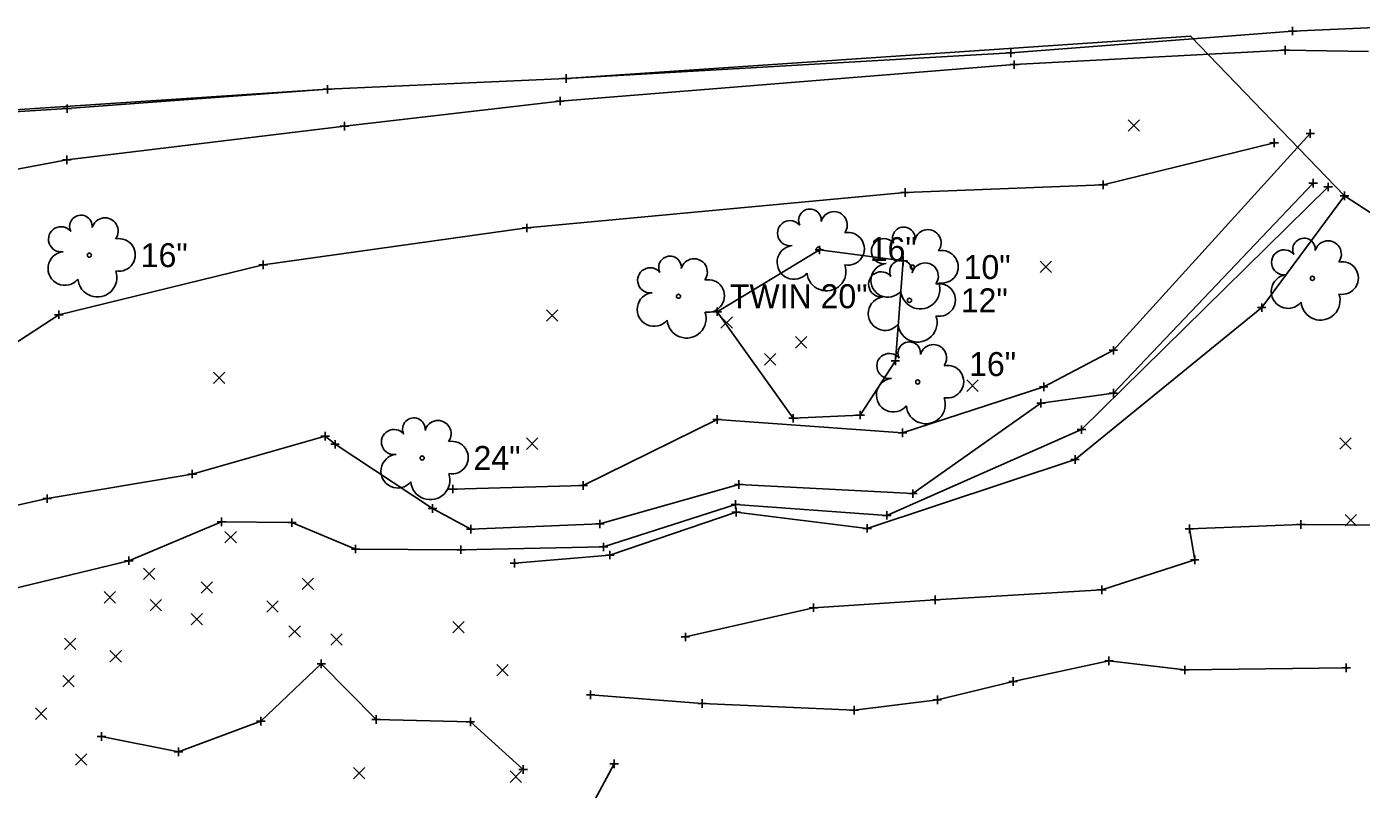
# Model space of a CAD drawing. Extents: x 203564 to 204038, y 344976 to 345157.
# Drawn here: x 203796.6 to 203952.6, y 345067.2 to 345156.4 of the extents above; entities that cross this region are included whole.
import ezdxf

# ---------------------------------------------------------------- set-up
doc = ezdxf.new("R2010")
doc.units = 0
for name, color, linetype in [('_CIVIL_CONSTRUCTION', 7, 'Continuous'), ('DR_X_Ditch', 7, 'Continuous'), ('RD_X_Fence', 7, 'Continuous'), ('RW_X_CL_100_Bearings', 7, 'Continuous'), ('RW_X_CL_100_Cardinal_Points', 7, 'Continuous'), ('SV_X_Break_Lines', 7, 'Continuous'), ('SV_X_Edge_of_Slip', 7, 'Continuous'), ('SV_X_Terrain_Boundary', 7, 'Continuous'), ('SV_X_Top_of_Bank', 7, 'Continuous'), ('VG_X_Text', 7, 'Continuous')]:
    doc.layers.add(name, color=color, linetype=linetype)

msp = doc.modelspace()

# ---------------------------------------------------------------- linework, layer by layer
at = {"layer": '_CIVIL_CONSTRUCTION'}
for p, q in [((203944.06, 345155.88), (203945.06, 345155.88)), ((203944.56, 345156.38), (203944.56, 345155.38)), ((203944.56, 345155.88), (203944.56, 345155.88)), ((203911.63, 345153.84), (203911.63, 345152.84)), ((203943.72, 345154.14), (203943.72, 345153.14)), ((203911.13, 345153.34), (203912.13, 345153.34)), ((203911.63, 345153.34), (203911.63, 345153.34)), ((203912.05, 345152.45), (203912.05, 345151.45)), ((203943.22, 345153.64), (203944.22, 345153.64)), ((203943.72, 345153.64), (203943.72, 345153.64)), ((203859.66, 345150.84), (203859.66, 345149.84)), ((203911.55, 345151.95), (203912.55, 345151.95)), ((203912.05, 345151.95), (203912.05, 345151.95)), ((203831.78, 345149.57), (203831.78, 345148.57)), ((203859.16, 345150.34), (203860.16, 345150.34)), ((203859.66, 345150.34), (203859.66, 345150.34)), ((203831.28, 345149.07), (203832.28, 345149.07)), ((203831.78, 345149.07), (203831.78, 345149.07)), ((203858.46, 345147.7), (203859.46, 345147.7)), ((203858.96, 345148.2), (203858.96, 345147.2)), ((203858.96, 345147.7), (203858.96, 345147.7)), ((203800.86, 345146.81), (203801.86, 345146.81)), ((203801.36, 345147.31), (203801.36, 345146.31)), ((203801.36, 345146.81), (203801.36, 345146.81)), ((203833.26, 345144.76), (203834.26, 345144.76)), ((203833.76, 345145.26), (203833.76, 345144.26)), ((203833.76, 345144.76), (203833.76, 345144.76)), ((203942.42, 345143.3), (203942.42, 345142.3)), ((203946.15, 345143.9), (203947.15, 345143.9)), ((203946.65, 345144.4), (203946.65, 345143.4)), ((203946.65, 345143.9), (203946.65, 345143.9)), ((203801.31, 345141.31), (203801.31, 345140.31)), ((203941.92, 345142.8), (203942.92, 345142.8)), ((203942.42, 345142.8), (203942.42, 345142.8)), ((203800.81, 345140.81), (203801.81, 345140.81)), ((203801.31, 345140.81), (203801.31, 345140.81)), ((203922.44, 345138.4), (203922.44, 345137.4)), ((203946.98, 345138.58), (203946.98, 345137.58)), ((203898.78, 345137.01), (203899.78, 345137.01)), ((203899.28, 345137.51), (203899.28, 345136.51)), ((203899.28, 345137.01), (203899.28, 345137.01)), ((203921.94, 345137.9), (203922.94, 345137.9)), ((203922.44, 345137.9), (203922.44, 345137.9)), ((203946.48, 345138.08), (203947.48, 345138.08)), ((203946.98, 345138.08), (203946.98, 345138.08)), ((203948.24, 345137.65), (203949.24, 345137.65)), ((203948.74, 345138.15), (203948.74, 345137.15)), ((203948.74, 345137.65), (203948.74, 345137.65)), ((203950.66, 345137.11), (203950.66, 345136.11)), ((203950.16, 345136.61), (203951.16, 345136.61)), ((203950.66, 345136.61), (203950.66, 345136.61)), ((203854.57, 345132.85), (203855.57, 345132.85)), ((203855.07, 345133.35), (203855.07, 345132.35)), ((203855.07, 345132.85), (203855.07, 345132.85)), ((203889.27, 345130.78), (203889.27, 345129.78)), ((203824.26, 345129.04), (203824.26, 345128.04)), ((203888.77, 345130.28), (203889.77, 345130.28)), ((203889.27, 345130.28), (203889.27, 345130.28)), ((203898.57, 345129.02), (203899.57, 345129.02)), ((203899.07, 345129.52), (203899.07, 345128.52)), ((203899.07, 345129.02), (203899.07, 345129.02)), ((203823.76, 345128.54), (203824.76, 345128.54)), ((203824.26, 345128.54), (203824.26, 345128.54)), ((203799.89, 345122.71), (203800.89, 345122.71)), ((203800.39, 345123.21), (203800.39, 345122.21)), ((203800.39, 345122.71), (203800.39, 345122.71)), ((203876.84, 345123.06), (203877.84, 345123.06)), ((203877.34, 345123.56), (203877.34, 345122.56)), ((203877.34, 345123.06), (203877.34, 345123.06)), ((203940.47, 345123.54), (203941.47, 345123.54)), ((203940.97, 345124.04), (203940.97, 345123.04)), ((203940.97, 345123.54), (203940.97, 345123.54)), ((203923.13, 345118.55), (203924.13, 345118.55)), ((203923.63, 345119.05), (203923.63, 345118.05)), ((203923.63, 345118.55), (203923.63, 345118.55)), ((203897.65, 345117.32), (203898.65, 345117.32)), ((203898.15, 345117.82), (203898.15, 345116.82)), ((203898.15, 345117.32), (203898.15, 345117.32)), ((203915.49, 345114.78), (203915.49, 345113.78)), ((203914.99, 345114.28), (203915.99, 345114.28)), ((203915.49, 345114.28), (203915.49, 345114.28)), ((203923.13, 345113.53), (203924.13, 345113.53)), ((203923.63, 345114.03), (203923.63, 345113.03)), ((203923.63, 345113.53), (203923.63, 345113.53)), ((203914.67, 345112.36), (203915.67, 345112.36)), ((203915.17, 345112.86), (203915.17, 345111.86)), ((203915.17, 345112.36), (203915.17, 345112.36)), ((203876.83, 345110.45), (203877.83, 345110.45)), ((203877.33, 345110.95), (203877.33, 345109.95)), ((203877.33, 345110.45), (203877.33, 345110.45)), ((203885.7, 345110.6), (203886.7, 345110.6)), ((203886.2, 345111.1), (203886.2, 345110.1)), ((203886.2, 345110.6), (203886.2, 345110.6)), ((203893.54, 345110.98), (203894.54, 345110.98)), ((203894.04, 345111.48), (203894.04, 345110.48)), ((203894.04, 345110.98), (203894.04, 345110.98)), ((203831.51, 345109.02), (203831.51, 345108.02)), ((203898.5, 345108.9), (203899.5, 345108.9)), ((203899, 345109.4), (203899, 345108.4)), ((203899, 345108.9), (203899, 345108.9)), ((203919.42, 345109.27), (203920.42, 345109.27)), ((203919.92, 345109.77), (203919.92, 345108.77)), ((203919.92, 345109.27), (203919.92, 345109.27)), ((203831.01, 345108.52), (203832.01, 345108.52)), ((203831.51, 345108.52), (203831.51, 345108.52)), ((203832.16, 345107.56), (203833.16, 345107.56)), ((203832.66, 345108.06), (203832.66, 345107.06)), ((203832.66, 345107.56), (203832.66, 345107.56)), ((203918.65, 345105.79), (203919.65, 345105.79)), ((203919.15, 345106.29), (203919.15, 345105.29)), ((203919.15, 345105.79), (203919.15, 345105.79)), ((203815.46, 345104.08), (203816.46, 345104.08)), ((203815.96, 345104.58), (203815.96, 345103.58)), ((203815.96, 345104.08), (203815.96, 345104.08)), ((203845.92, 345102.33), (203846.92, 345102.33)), ((203846.42, 345102.83), (203846.42, 345101.83)), ((203846.42, 345102.33), (203846.42, 345102.33)), ((203861.16, 345102.75), (203862.16, 345102.75)), ((203861.66, 345103.25), (203861.66, 345102.25)), ((203861.66, 345102.75), (203861.66, 345102.75)), ((203879.35, 345102.86), (203880.35, 345102.86)), ((203879.85, 345103.36), (203879.85, 345102.36)), ((203879.85, 345102.86), (203879.85, 345102.86)), ((203798.52, 345101.2), (203799.52, 345101.2)), ((203799.02, 345101.7), (203799.02, 345100.7)), ((203799.02, 345101.2), (203799.02, 345101.2)), ((203879.46, 345101.01), (203879.46, 345100.01)), ((203899.71, 345101.79), (203900.71, 345101.79)), ((203900.21, 345102.29), (203900.21, 345101.29)), ((203900.21, 345101.79), (203900.21, 345101.79)), ((203843.56, 345100.06), (203844.56, 345100.06)), ((203844.06, 345100.56), (203844.06, 345099.56)), ((203844.06, 345100.06), (203844.06, 345100.06)), ((203878.96, 345100.51), (203879.96, 345100.51)), ((203879.04, 345099.63), (203880.04, 345099.63)), ((203879.46, 345100.51), (203879.46, 345100.51)), ((203879.54, 345100.13), (203879.54, 345099.13)), ((203879.54, 345099.63), (203879.54, 345099.63)), ((203896.66, 345099.25), (203897.66, 345099.25)), ((203897.16, 345099.75), (203897.16, 345098.75)), ((203897.16, 345099.25), (203897.16, 345099.25)), ((203818.9, 345098.49), (203819.9, 345098.49)), ((203819.4, 345098.99), (203819.4, 345097.99)), ((203819.4, 345098.49), (203819.4, 345098.49)), ((203827.13, 345098.4), (203828.13, 345098.4)), ((203827.63, 345098.9), (203827.63, 345097.9)), ((203827.63, 345098.4), (203827.63, 345098.4)), ((203848.02, 345097.64), (203849.02, 345097.64)), ((203848.52, 345098.14), (203848.52, 345097.14)), ((203848.52, 345097.64), (203848.52, 345097.64)), ((203863.13, 345098.24), (203864.13, 345098.24)), ((203863.63, 345098.74), (203863.63, 345097.74)), ((203863.63, 345098.24), (203863.63, 345098.24)), ((203894.37, 345097.73), (203895.37, 345097.73)), ((203894.87, 345098.23), (203894.87, 345097.23)), ((203894.87, 345097.73), (203894.87, 345097.73)), ((203932.02, 345097.67), (203933.02, 345097.67)), ((203932.52, 345098.17), (203932.52, 345097.17)), ((203932.52, 345097.67), (203932.52, 345097.67)), ((203945.04, 345098.18), (203946.04, 345098.18)), ((203945.54, 345098.68), (203945.54, 345097.68)), ((203945.54, 345098.18), (203945.54, 345098.18)), ((203834.57, 345095.31), (203835.57, 345095.31)), ((203835.07, 345095.81), (203835.07, 345094.81)), ((203835.07, 345095.31), (203835.07, 345095.31)), ((203846.88, 345095.23), (203847.88, 345095.23)), ((203847.38, 345095.73), (203847.38, 345094.73)), ((203847.38, 345095.23), (203847.38, 345095.23)), ((203863.54, 345095.55), (203864.54, 345095.55)), ((203864.04, 345096.05), (203864.04, 345095.05)), ((203864.04, 345095.55), (203864.04, 345095.55)), ((203864.28, 345094.61), (203865.28, 345094.61)), ((203864.78, 345095.11), (203864.78, 345094.11)), ((203864.78, 345094.61), (203864.78, 345094.61)), ((203933.14, 345094.54), (203933.14, 345093.54)), ((203808.07, 345093.95), (203809.07, 345093.95)), ((203808.57, 345094.45), (203808.57, 345093.45)), ((203808.57, 345093.95), (203808.57, 345093.95)), ((203853.12, 345093.67), (203854.12, 345093.67)), ((203853.62, 345094.17), (203853.62, 345093.17)), ((203853.62, 345093.67), (203853.62, 345093.67)), ((203932.64, 345094.04), (203933.64, 345094.04)), ((203933.14, 345094.04), (203933.14, 345094.04)), ((203902.81, 345089.86), (203902.81, 345088.86)), ((203921.79, 345090.53), (203922.79, 345090.53)), ((203922.29, 345091.03), (203922.29, 345090.03)), ((203922.29, 345090.53), (203922.29, 345090.53)), ((203888.09, 345088.45), (203889.09, 345088.45)), ((203888.59, 345088.95), (203888.59, 345087.95)), ((203888.59, 345088.45), (203888.59, 345088.45)), ((203902.31, 345089.36), (203903.31, 345089.36)), ((203902.81, 345089.36), (203902.81, 345089.36)), ((203873.61, 345085.53), (203873.61, 345084.53)), ((203873.11, 345085.03), (203874.11, 345085.03)), ((203873.61, 345085.03), (203873.61, 345085.03)), ((203831.06, 345082.39), (203831.06, 345081.39)), ((203922.62, 345082.24), (203923.62, 345082.24)), ((203923.12, 345082.74), (203923.12, 345081.74)), ((203923.12, 345082.24), (203923.12, 345082.24)), ((203830.56, 345081.89), (203831.56, 345081.89)), ((203831.06, 345081.89), (203831.06, 345081.89)), ((203931.49, 345081.17), (203932.49, 345081.17)), ((203931.99, 345081.67), (203931.99, 345080.67)), ((203931.99, 345081.17), (203931.99, 345081.17)), ((203950.36, 345081.42), (203951.36, 345081.42)), ((203950.86, 345081.92), (203950.86, 345080.92)), ((203950.86, 345081.42), (203950.86, 345081.42)), ((203911.41, 345079.81), (203912.41, 345079.81)), ((203911.91, 345080.31), (203911.91, 345079.31)), ((203911.91, 345079.81), (203911.91, 345079.81)), ((203862.04, 345078.26), (203863.04, 345078.26)), ((203862.54, 345078.76), (203862.54, 345077.76)), ((203862.54, 345078.26), (203862.54, 345078.26)), ((203875.57, 345077.76), (203875.57, 345076.76)), ((203902.56, 345077.67), (203903.56, 345077.67)), ((203903.06, 345078.17), (203903.06, 345077.17)), ((203903.06, 345077.67), (203903.06, 345077.67)), ((203837.47, 345075.89), (203837.47, 345074.89)), ((203875.07, 345077.26), (203876.07, 345077.26)), ((203875.57, 345077.26), (203875.57, 345077.26)), ((203892.83, 345076.47), (203893.83, 345076.47)), ((203893.33, 345076.97), (203893.33, 345075.97)), ((203893.33, 345076.47), (203893.33, 345076.47)), ((203823.48, 345075.19), (203824.48, 345075.19)), ((203823.98, 345075.69), (203823.98, 345074.69)), ((203823.98, 345075.19), (203823.98, 345075.19)), ((203836.97, 345075.39), (203837.97, 345075.39)), ((203837.47, 345075.39), (203837.47, 345075.39)), ((203847.98, 345075.1), (203848.98, 345075.1)), ((203848.48, 345075.6), (203848.48, 345074.6)), ((203848.48, 345075.1), (203848.48, 345075.1)), ((203804.86, 345073.4), (203805.86, 345073.4)), ((203805.36, 345073.9), (203805.36, 345072.9)), ((203805.36, 345073.4), (203805.36, 345073.4)), ((203813.86, 345071.6), (203814.86, 345071.6)), ((203814.36, 345072.1), (203814.36, 345071.1)), ((203814.36, 345071.6), (203814.36, 345071.6)), ((203854.14, 345069.53), (203855.14, 345069.53)), ((203854.64, 345070.03), (203854.64, 345069.03)), ((203854.64, 345069.53), (203854.64, 345069.53)), ((203864.79, 345070.2), (203865.79, 345070.2)), ((203865.29, 345070.7), (203865.29, 345069.7)), ((203865.29, 345070.2), (203865.29, 345070.2))]:
    msp.add_line(p, q, dxfattribs=at)
at = {"layer": 'DR_X_Ditch'}
msp.add_lwpolyline([(203645.13, 345073.88), (203663.45, 345073.36), (203684.09, 345074.74), (203711.42, 345078.8), (203737.16, 345081.33), (203746.21, 345089.02), (203763.55, 345098.37), (203783.18, 345097.67), (203799.02, 345101.2), (203815.96, 345104.08), (203831.51, 345108.52), (203832.66, 345107.56), (203844.06, 345100.06), (203848.52, 345097.64), (203863.63, 345098.24), (203879.85, 345102.86), (203900.21, 345101.79), (203915.17, 345112.36), (203923.63, 345113.53), (203946.98, 345138.08)], dxfattribs=at)
at = {"layer": 'RD_X_Fence'}
msp.add_lwpolyline([(203689.69, 345139.7), (203694.78, 345139.75), (203716.34, 345141.29), (203756.25, 345143.96), (203801.36, 345146.81), (203831.78, 345149.07), (203859.66, 345150.34), (203911.63, 345153.34), (203944.56, 345155.88), (203956.03, 345156.39)], dxfattribs=at)
at = {"layer": 'RW_X_CL_100_Bearings'}
for p, q in [((203925.36, 345144.16), (203926.7, 345145.49)), ((203925.36, 345145.49), (203926.7, 345144.16)), ((203915.06, 345127.64), (203916.39, 345128.98)), ((203915.06, 345128.98), (203916.39, 345127.64)), ((203857.37, 345121.94), (203858.7, 345123.27)), ((203857.37, 345123.27), (203858.7, 345121.94)), ((203877.76, 345121.12), (203879.1, 345122.45)), ((203877.76, 345122.45), (203879.1, 345121.12)), ((203886.47, 345118.81), (203887.8, 345120.15)), ((203886.47, 345120.15), (203887.8, 345118.81)), ((203882.84, 345116.83), (203884.17, 345118.16)), ((203882.84, 345118.16), (203884.17, 345116.83)), ((203818.46, 345114.68), (203819.79, 345116.01)), ((203818.46, 345116.01), (203819.79, 345114.68)), ((203906.51, 345113.74), (203907.84, 345115.08)), ((203906.51, 345115.08), (203907.84, 345113.74)), ((203855.03, 345106.96), (203856.37, 345108.3)), ((203855.03, 345108.3), (203856.37, 345106.96)), ((203950.09, 345106.97), (203951.43, 345108.3)), ((203950.09, 345108.3), (203951.43, 345106.97)), ((203950.72, 345098.02), (203952.06, 345099.36)), ((203950.72, 345099.36), (203952.06, 345098.02)), ((203819.8, 345096.04), (203821.14, 345097.38)), ((203819.8, 345097.38), (203821.14, 345096.04)), ((203810.26, 345091.74), (203811.6, 345093.08)), ((203810.26, 345093.08), (203811.6, 345091.74)), ((203817.02, 345090.14), (203818.35, 345091.48)), ((203817.02, 345091.48), (203818.35, 345090.14)), ((203828.81, 345090.56), (203830.15, 345091.9)), ((203828.81, 345091.9), (203830.15, 345090.56)), ((203805.68, 345088.99), (203807.01, 345090.33)), ((203805.68, 345090.33), (203807.01, 345088.99)), ((203811.04, 345088.08), (203812.37, 345089.41)), ((203811.04, 345089.41), (203812.37, 345088.08)), ((203824.68, 345087.93), (203826.02, 345089.27)), ((203824.68, 345089.27), (203826.02, 345087.93)), ((203815.85, 345086.45), (203817.19, 345087.79)), ((203815.85, 345087.79), (203817.19, 345086.45)), ((203846.43, 345085.51), (203847.76, 345086.85)), ((203846.43, 345086.85), (203847.76, 345085.51)), ((203827.28, 345085), (203828.61, 345086.33)), ((203827.28, 345086.33), (203828.61, 345085)), ((203832.17, 345084.06), (203833.5, 345085.4)), ((203832.17, 345085.4), (203833.5, 345084.06)), ((203801.03, 345083.55), (203802.36, 345084.89)), ((203801.03, 345084.89), (203802.36, 345083.55)), ((203806.36, 345082.1), (203807.69, 345083.43)), ((203806.36, 345083.43), (203807.69, 345082.1)), ((203800.84, 345079.2), (203802.18, 345080.54)), ((203800.84, 345080.54), (203802.18, 345079.2)), ((203851.56, 345080.48), (203852.89, 345081.82)), ((203851.56, 345081.82), (203852.89, 345080.48)), ((203797.64, 345075.39), (203798.98, 345076.73)), ((203797.64, 345076.73), (203798.98, 345075.39)), ((203802.33, 345070.04), (203803.66, 345071.38)), ((203802.33, 345071.38), (203803.66, 345070.04)), ((203834.81, 345068.44), (203836.14, 345069.78)), ((203834.81, 345069.78), (203836.14, 345068.44)), ((203853.13, 345068.02), (203854.46, 345069.36)), ((203853.13, 345069.36), (203854.46, 345068.02))]:
    msp.add_line(p, q, dxfattribs=at)
at = {"layer": 'RW_X_CL_100_Cardinal_Points'}
for centre in [(203889.16, 345130.38), (203803.95, 345129.67), (203900.13, 345128.28), (203946.9, 345126.97), (203872.81, 345124.87), (203899.8, 345124.39), (203900.77, 345114.84), (203842.85, 345105.96)]:
    msp.add_circle(centre, 0.24, dxfattribs=at)
for centre, radius, start, end in [((203888.17, 345133.75), 1.32, 354.0047, 205.9741), ((203802.96, 345133.03), 1.32, 354.0047, 205.9741), ((203805.77, 345132.49), 1.55, 323.83, 165.0376), ((203885.85, 345132.24), 1.47, 39.0625, 279.5412), ((203890.98, 345133.21), 1.55, 323.83, 165.0376), ((203800.64, 345131.53), 1.47, 39.0625, 279.5412), ((203892.62, 345130.42), 1.91, 259.1453, 101.4596), ((203899.14, 345131.64), 1.32, 354.0047, 205.9741), ((203901.95, 345131.11), 1.55, 323.83, 165.0376), ((203807.41, 345129.7), 1.91, 259.1453, 101.4596), ((203886.3, 345128.83), 1.97, 96.1722, 320.5737), ((203896.82, 345130.14), 1.47, 39.0625, 279.5412), ((203945.92, 345130.34), 1.32, 354.0047, 205.9741), ((203948.73, 345129.8), 1.55, 323.83, 165.0376), ((203801.09, 345128.12), 1.97, 96.1722, 320.5737), ((203871.82, 345128.24), 1.32, 354.0047, 205.9741), ((203874.63, 345127.7), 1.55, 323.83, 165.0376), ((203898.82, 345127.76), 1.32, 354.0047, 205.9741), ((203903.59, 345128.31), 1.91, 259.1453, 101.4596), ((203943.59, 345128.83), 1.47, 39.0625, 279.5412), ((203950.36, 345127), 1.91, 259.1453, 101.4596), ((203804.89, 345127.06), 2.28, 184.9476, 19.4572), ((203869.5, 345126.73), 1.47, 39.0625, 279.5412), ((203890.1, 345127.78), 2.28, 184.9476, 19.4572), ((203896.5, 345126.26), 1.47, 39.0625, 279.5412), ((203897.27, 345126.73), 1.97, 96.1722, 320.5737), ((203901.63, 345127.22), 1.55, 323.83, 165.0376), ((203944.05, 345125.42), 1.97, 96.1722, 320.5737), ((203876.27, 345124.9), 1.91, 259.1453, 101.4596), ((203901.07, 345125.67), 2.28, 184.9476, 19.4572), ((203903.26, 345124.43), 1.91, 259.1453, 101.4596), ((203869.95, 345123.32), 1.97, 96.1722, 320.5737), ((203896.95, 345122.84), 1.97, 96.1722, 320.5737), ((203947.85, 345124.36), 2.28, 184.9476, 19.4572), ((203873.75, 345122.26), 2.28, 184.9476, 19.4572), ((203900.75, 345121.79), 2.28, 184.9476, 19.4572), ((203899.78, 345118.21), 1.32, 354.0047, 205.9741), ((203897.46, 345116.71), 1.47, 39.0625, 279.5412), ((203902.59, 345117.67), 1.55, 323.83, 165.0376), ((203904.23, 345114.88), 1.91, 259.1453, 101.4596), ((203897.91, 345113.3), 1.97, 96.1722, 320.5737), ((203901.71, 345112.24), 2.28, 184.9476, 19.4572), ((203841.87, 345109.33), 1.32, 354.0047, 205.9741), ((203844.68, 345108.79), 1.55, 323.83, 165.0376), ((203839.55, 345107.82), 1.47, 39.0625, 279.5412), ((203846.32, 345106), 1.91, 259.1453, 101.4596), ((203840, 345104.41), 1.97, 96.1722, 320.5737), ((203843.8, 345103.36), 2.28, 184.9476, 19.4572)]:
    msp.add_arc(centre, radius, start, end, dxfattribs=at)
at = {"layer": 'SV_X_Break_Lines'}
for points in [[(203953.45, 345153.5), (203943.72, 345153.64), (203912.05, 345151.95), (203858.96, 345147.7), (203833.76, 345144.76), (203801.31, 345140.81), (203779.13, 345136.66), (203777.12, 345135.45), (203752.42, 345126.52), (203746.41, 345122.24), (203728.59, 345114.72)], [(203846.42, 345102.33), (203861.66, 345102.75), (203877.33, 345110.45), (203899, 345108.9), (203915.49, 345114.28), (203923.63, 345118.55), (203946.65, 345143.9)], [(203789.34, 345115.54), (203800.39, 345122.71), (203824.26, 345128.54), (203855.07, 345132.85), (203899.28, 345137.01), (203922.44, 345137.9), (203942.42, 345142.8)], [(203645.79, 345070.3), (203666.12, 345070.74), (203684.33, 345071.75), (203710.63, 345074.99), (203738.19, 345078.94), (203749.36, 345081.5), (203755.67, 345083.94), (203767, 345085.5), (203793.88, 345090.38), (203808.57, 345093.95), (203819.4, 345098.49), (203827.63, 345098.4), (203835.07, 345095.31), (203847.38, 345095.23), (203864.04, 345095.55), (203879.46, 345100.51), (203897.16, 345099.25), (203919.92, 345109.27), (203948.74, 345137.65)], [(203854.64, 345069.53), (203848.48, 345075.1), (203837.47, 345075.39), (203831.06, 345081.89), (203823.98, 345075.19), (203814.36, 345071.6), (203805.36, 345073.4)]]:
    msp.add_lwpolyline(points, dxfattribs=at)
msp.add_lwpolyline([(203899.07, 345129.02), (203898.15, 345117.32), (203894.04, 345110.98), (203886.2, 345110.6), (203877.34, 345123.06), (203889.27, 345130.28)], close=True, dxfattribs=at)
at = {"layer": 'SV_X_Edge_of_Slip'}
for points in [[(203873.61, 345085.03), (203888.59, 345088.45), (203902.81, 345089.36), (203922.29, 345090.53), (203933.14, 345094.04), (203932.52, 345097.67), (203945.54, 345098.18), (203961.23, 345098.08)], [(203950.86, 345081.42), (203931.99, 345081.17), (203923.12, 345082.24), (203911.91, 345079.81), (203903.06, 345077.67), (203893.33, 345076.47), (203875.57, 345077.26), (203862.54, 345078.26)], [(203795.1, 345010.01), (203802.98, 345006.85), (203808.1, 345004.55), (203816.55, 345005.3), (203824.66, 345004.1), (203829.04, 345006.1), (203831.71, 345005.14), (203834.76, 345004.72), (203837.85, 345006.51), (203839.5, 345004.71), (203843.12, 345004.19), (203845.89, 345006.3), (203849.46, 345007.18), (203853.43, 345006.53), (203857.49, 345011.66), (203858.32, 345016.96), (203858.17, 345025.51), (203857.59, 345030.7), (203856.34, 345044.15), (203855.09, 345051.18), (203865.29, 345070.2)]]:
    msp.add_lwpolyline(points, dxfattribs=at)
at = {"layer": 'SV_X_Terrain_Boundary'}
msp.add_lwpolyline([(203688.25, 345107.3), (203663.45, 345073.36), (203661.3, 344976.54), (203725.72, 344980.7), (203774.29, 344983.85), (203870.66, 344990.35), (203921.82, 344994.21), (203965.84, 344997.53), (203960.08, 345013.12), (203981.66, 345100.71), (203974.83, 345120.91), (203950.66, 345136.61), (203932.67, 345155.23), (203932.67, 345155.29), (203859.66, 345150.34), (203831.78, 345149.07), (203795.84, 345146.71), (203756.25, 345143.96), (203689.69, 345139.7)], close=True, dxfattribs=at)
at = {"layer": 'SV_X_Top_of_Bank'}
msp.add_lwpolyline([(203853.62, 345093.67), (203864.78, 345094.61), (203879.54, 345099.63), (203894.87, 345097.73), (203919.15, 345105.79), (203940.97, 345123.54), (203950.66, 345136.61)], dxfattribs=at)

# ---------------------------------------------------------------- texts
at = {"layer": 'VG_X_Text'}
for s, p in [('16"', (203809.95, 345128.27)), ('16"', (203895.16, 345128.98)), ('10"', (203906.13, 345126.88)), ('TWIN 20"', (203878.81, 345123.47)), ('12"', (203905.8, 345122.99)), ('16"', (203906.77, 345115.54)), ('24"', (203848.85, 345104.56))]:
    msp.add_text(s, height=2.8, dxfattribs=at).set_placement(p)

doc.saveas('drawing.dxf')
